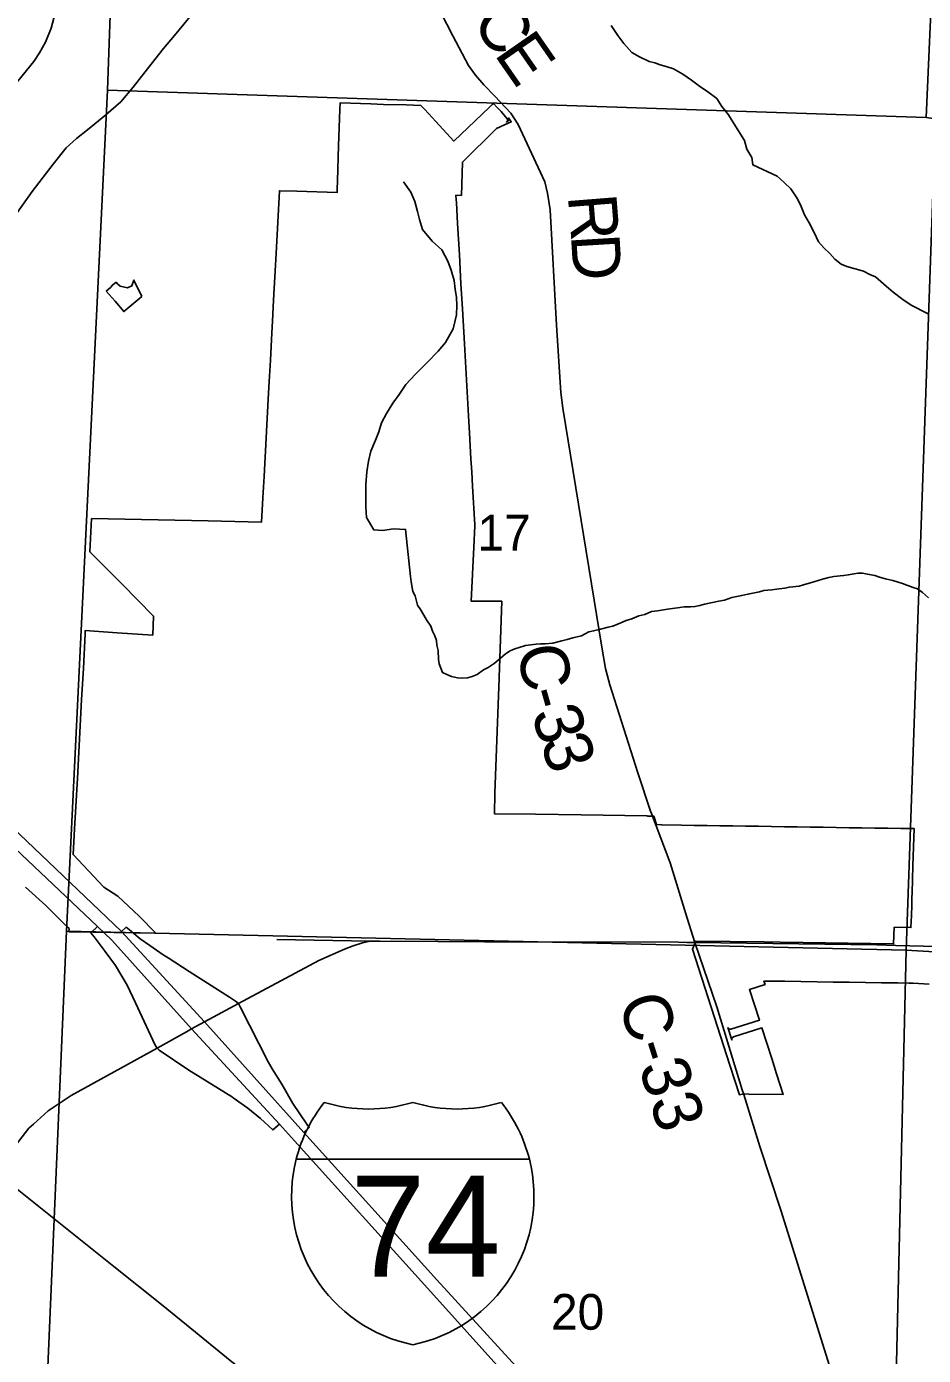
# Model space of a CAD drawing. Extents: x -7.5 to 26.5, y 3.5 to 25.5.
# Drawn here: x -4.268 to -3.216, y 21.705 to 23.263 of the extents above; entities that cross this region are included whole.
import ezdxf

# ---------------------------------------------------------------- set-up
doc = ezdxf.new("R2010")
doc.units = 0
for name, color, linetype in [('GM_X_City_Street', 7, 'Continuous'), ('GM_X_Corporation', 7, 'Continuous'), ('GM_X_County_Road', 7, 'Continuous'), ('GM_X_County_Road_Text', 7, 'Continuous'), ('GM_X_Interchange_Ramps', 7, 'Continuous'), ('GM_X_Interstate_Location', 7, 'Continuous'), ('GM_X_Interstate_Route', 7, 'Continuous'), ('GM_X_Interstate_Shield', 7, 'Continuous'), ('GM_X_Minor_River', 7, 'Continuous'), ('GM_X_Section_Text', 7, 'Continuous'), ('GM_X_US_Route', 7, 'Continuous')]:
    doc.layers.add(name, color=color, linetype=linetype)

msp = doc.modelspace()

# ---------------------------------------------------------------- linework, layer by layer
at = {"layer": 'GM_X_City_Street'}
msp.add_line((-3.9745, 22.1926), (-3.8649, 22.1905), dxfattribs=at)
at = {"layer": 'GM_X_Corporation'}
for points in [[(-4.138, 24.1781), (-3.1693, 24.148), (-3.2132, 23.1565), (-4.1729, 23.1886)], [(-4.1729, 23.1886), (-3.2132, 23.1565), (-3.2023, 23.155), (-3.2367, 22.18), (-4.2212, 22.2025)], [(-3.2023, 23.155), (-2.1999, 23.1078), (-2.2479, 22.1217), (-3.2367, 22.18)], [(-4.2212, 22.2025), (-3.2367, 22.18), (-3.2602, 21.1789), (-4.2641, 21.1987)], [(-3.2367, 22.18), (-2.2479, 22.1217), (-2.268, 21.1618), (-3.2602, 21.1789)]]:
    msp.add_lwpolyline(points, close=True, dxfattribs=at)
msp.add_lwpolyline([(-4.269, 22.2541), (-4.2451, 22.2323), (-4.2206, 22.2079), (-4.2181, 22.2054), (-4.2183, 22.2016), (-4.2144, 22.2015), (-4.1162, 22.2001), (-4.136, 22.22), (-4.1609, 22.2432), (-4.1774, 22.2538), (-4.2133, 22.2921), (-4.2125, 22.307), (-4.2117, 22.3223), (-4.2082, 22.3813), (-4.2033, 22.4739), (-4.2013, 22.5105), (-4.1992, 22.551), (-4.199, 22.555), (-4.1618, 22.5524), (-4.12, 22.5496), (-4.1189, 22.5716), (-4.1563, 22.6098), (-4.1937, 22.6473), (-4.1916, 22.6862), (-4.0548, 22.6836), (-3.9923, 22.6822), (-3.9908, 22.7107), (-3.9894, 22.7356), (-3.9886, 22.7507), (-3.9878, 22.7659), (-3.987, 22.781), (-3.9862, 22.7961), (-3.9853, 22.8112), (-3.9845, 22.8264), (-3.9834, 22.8472), (-3.9821, 22.8719), (-3.9803, 22.9042), (-3.9796, 22.9178), (-3.9783, 22.9426), (-3.9753, 22.997), (-3.9714, 23.0707), (-3.9512, 23.0701), (-3.9039, 23.0686), (-3.9038, 23.0714), (-3.9038, 23.0718), (-3.903, 23.0948), (-3.9024, 23.1107), (-3.902, 23.1235), (-3.9005, 23.1662), (-3.9003, 23.1738), (-3.8641, 23.1726), (-3.8494, 23.1721), (-3.8227, 23.1714), (-3.8055, 23.1709), (-3.801, 23.166), (-3.788, 23.1519), (-3.7671, 23.1291), (-3.7253, 23.1686), (-3.7219, 23.1719), (-3.7205, 23.1732), (-3.716, 23.1684), (-3.7116, 23.1637), (-3.708, 23.1596), (-3.7046, 23.1553), (-3.7044, 23.1549), (-3.7042, 23.1545), (-3.7041, 23.1541), (-3.704, 23.1537), (-3.7041, 23.1532), (-3.7042, 23.1528), (-3.7043, 23.1524), (-3.7046, 23.152), (-3.7047, 23.1519), (-3.705, 23.1515), (-3.7054, 23.1512), (-3.7044, 23.1518), (-3.7038, 23.1522), (-3.7034, 23.1525), (-3.7031, 23.1528), (-3.7028, 23.1531), (-3.7026, 23.1536), (-3.7025, 23.154), (-3.7024, 23.1544), (-3.7024, 23.1549), (-3.7025, 23.1553), (-3.7027, 23.1558), (-3.7029, 23.1562), (-3.6997, 23.1514), (-3.7031, 23.1499), (-3.717, 23.1437), (-3.7569, 23.1042), (-3.758, 23.0652), (-3.7645, 23.0654), (-3.7642, 23.06), (-3.764, 23.0569), (-3.7626, 23.0322), (-3.7605, 22.9954), (-3.7586, 22.9615), (-3.7569, 22.9324), (-3.7546, 22.8912), (-3.7497, 22.8069), (-3.7486, 22.7867), (-3.7477, 22.7714), (-3.7469, 22.7562), (-3.746, 22.741), (-3.745, 22.7242), (-3.7424, 22.679), (-3.7424, 22.6779), (-3.7436, 22.6527), (-3.7465, 22.5892), (-3.7108, 22.5893), (-3.7139, 22.5), (-3.7139, 22.4989), (-3.7188, 22.3641), (-3.7195, 22.3401), (-3.6711, 22.3394), (-3.6176, 22.3386), (-3.5406, 22.3375), (-3.5395, 22.3374), (-3.5326, 22.3373), (-3.5292, 22.3273), (-3.5237, 22.327), (-3.5231, 22.327), (-3.5, 22.3266), (-3.4851, 22.3264), (-3.4701, 22.3262), (-3.4552, 22.326), (-3.44, 22.3257), (-3.4249, 22.3255), (-3.4097, 22.3253), (-3.3946, 22.3251), (-3.3794, 22.3248), (-3.3643, 22.3246), (-3.3491, 22.3244), (-3.334, 22.3242), (-3.3188, 22.3239), (-3.3037, 22.3237), (-3.2885, 22.3235), (-3.2734, 22.3233), (-3.2582, 22.323), (-3.2431, 22.3228), (-3.2274, 22.3226), (-3.2284, 22.2904), (-3.2287, 22.279), (-3.2298, 22.2469), (-3.2299, 22.242), (-3.2302, 22.2326), (-3.2306, 22.2208), (-3.2311, 22.2066), (-3.2507, 22.207), (-3.2515, 22.1873), (-3.3839, 22.1894), (-3.4028, 22.1897), (-3.4834, 22.1907), (-3.4872, 22.1812), (-3.4434, 22.0453), (-3.4376, 22.0272), (-3.4322, 22.0104), (-3.4269, 22.0114), (-3.421, 22.0113), (-3.3809, 22.0107), (-3.3886, 22.0349), (-3.3943, 22.0529), (-3.4001, 22.071), (-3.4058, 22.0889), (-3.4392, 22.0783), (-3.4396, 22.0781), (-3.4401, 22.0778), (-3.4404, 22.0775), (-3.4407, 22.0771), (-3.441, 22.0767), (-3.4411, 22.0762), (-3.4412, 22.0757), (-3.4411, 22.0752), (-3.441, 22.0747), (-3.4456, 22.0892), (-3.4454, 22.0887), (-3.4452, 22.0883), (-3.4448, 22.0879), (-3.4444, 22.0876), (-3.444, 22.0874), (-3.4435, 22.0872), (-3.443, 22.0872), (-3.4425, 22.0872), (-3.4421, 22.0873), (-3.4087, 22.0979), (-3.4144, 22.1161), (-3.4202, 22.134), (-3.4021, 22.1398), (-3.4034, 22.1438), (-3.398, 22.1438), (-3.3791, 22.1435), (-3.3602, 22.1432), (-3.3412, 22.143), (-3.3223, 22.1427), (-3.3034, 22.1425), (-3.2844, 22.1422), (-3.2655, 22.1419), (-3.2465, 22.1417), (-3.2337, 22.1415), (-3.2286, 22.1412), (-3.2097, 22.14)], dxfattribs=at)
at = {"layer": 'GM_X_County_Road'}
for p, q in [((-3.4843, 22.1889), (-3.4933, 22.2175)), ((-4.0542, 22.0988), (-4.0196, 22.1174))]:
    msp.add_line(p, q, dxfattribs=at)
for points in [[(-4.3557, 23.0673), (-4.3318, 23.1095), (-4.3115, 23.1487), (-4.2883, 23.1867), (-4.2592, 23.2222), (-4.2527, 23.2325), (-4.2455, 23.245), (-4.239, 23.2613), (-4.2197, 23.3335), (-4.2114, 23.3542), (-4.165, 23.4496), (-4.1546, 23.4697), (-4.148, 23.482), (-4.1366, 23.4992), (-4.1272, 23.5096), (-4.1173, 23.5179), (-4.0908, 23.54), (-4.0744, 23.5582), (-4.0689, 23.5712), (-4.0648, 23.5832)], [(-4.442, 22.6063), (-4.4334, 22.6189), (-4.4176, 22.654), (-4.3877, 22.7241), (-4.3725, 22.7693), (-4.3633, 22.8101), (-4.3488, 22.8633), (-4.342, 22.8894), (-4.3327, 22.9169), (-4.3053, 22.9874), (-4.2936, 23.0185), (-4.2858, 23.0352), (-4.2614, 23.0699), (-4.2366, 23.1021), (-4.2215, 23.121), (-4.2094, 23.1319), (-4.1964, 23.1423), (-4.1751, 23.1597), (-4.1572, 23.1752), (-4.1429, 23.1922), (-4.122, 23.2193), (-4.1074, 23.2375), (-4.0945, 23.253), (-4.0327, 23.3282)], [(-3.5353, 22.3402), (-3.5363, 22.3429), (-3.5514, 22.3881), (-3.5842, 22.4913), (-3.5891, 22.5104), (-3.5935, 22.5356), (-3.6393, 22.8156), (-3.6415, 22.8342), (-3.6466, 22.9131), (-3.6539, 23.0482), (-3.657, 23.0679), (-3.6604, 23.0812), (-3.6916, 23.1485), (-3.7002, 23.1618), (-3.7191, 23.1816), (-3.7317, 23.1948), (-3.7414, 23.2063), (-3.7499, 23.2176), (-3.768, 23.2524), (-3.7825, 23.2807)], [(-3.4933, 22.2175), (-3.5135, 22.2824), (-3.5353, 22.3402)], [(-4.0196, 22.1174), (-3.9252, 22.1679), (-3.8952, 22.1813), (-3.885, 22.1853), (-3.8739, 22.1886), (-3.8649, 22.1905)], [(-3.8649, 22.1905), (-3.8539, 22.1905), (-3.7859, 22.1902), (-3.731, 22.19), (-3.7224, 22.19)], [(-3.7224, 22.19), (-3.5035, 22.1893), (-3.494, 22.1891)], [(-3.494, 22.1891), (-3.4892, 22.189), (-3.4843, 22.1889)], [(-3.4288, 22.0164), (-3.4586, 22.1135), (-3.4843, 22.1889)], [(-3.4843, 22.1889), (-3.2712, 22.1863), (-3.2487, 22.1857), (-3.2, 22.1843), (-3.1124, 22.1784), (-3.0958, 22.1773), (-3.0867, 22.1766)], [(-4.0805, 22.0844), (-4.0745, 22.0878), (-4.0594, 22.096), (-4.0542, 22.0988)], [(-4.3045, 21.9204), (-4.2653, 21.9711), (-4.2599, 21.9759), (-4.2427, 21.9915), (-4.2156, 22.0097), (-4.1146, 22.0653), (-4.0805, 22.0844)], [(-3.3225, 21.6802), (-3.3837, 21.875), (-3.4084, 21.9498), (-3.4271, 22.0107), (-3.4288, 22.0164)], [(-4.3045, 21.9204), (-4.2849, 21.9046), (-4.1655, 21.8092), (-4.1097, 21.7644)], [(-4.1097, 21.7644), (-4.1035, 21.7594), (-4.07, 21.7319), (-4.0292, 21.6988), (-3.9899, 21.668), (-3.9853, 21.6643)]]:
    msp.add_lwpolyline(points, dxfattribs=at)
at = {"layer": 'GM_X_Interchange_Ramps'}
for points in [[(-4.1846, 22.2079), (-4.1927, 22.2005), (-4.1887, 22.1957), (-4.1757, 22.1785), (-4.1638, 22.162), (-4.1499, 22.1389), (-4.14, 22.1181), (-4.1172, 22.0687), (-4.1146, 22.0653)], [(-4.1423, 22.1996), (-4.1474, 22.2038), (-4.1513, 22.2069), (-4.1567, 22.202)], [(-4.1019, 22.1709), (-4.1076, 22.1746), (-4.1235, 22.1855), (-4.1346, 22.1932), (-4.1423, 22.1996)], [(-4.0196, 22.1174), (-4.0231, 22.1204), (-4.0298, 22.1251), (-4.0772, 22.1549), (-4.1019, 22.1709)], [(-3.9798, 22.041), (-3.9848, 22.0492), (-4.0173, 22.1134), (-4.0196, 22.1174)], [(-4.1146, 22.0653), (-4.1123, 22.0626), (-4.0777, 22.0393), (-4.0427, 22.0178), (-4.0266, 22.0075)], [(-3.9428, 21.9662), (-3.9364, 21.9721), (-3.9392, 21.9759), (-3.9557, 22.0004), (-3.9687, 22.0227), (-3.9798, 22.041)], [(-4.0266, 22.0075), (-4.0257, 22.0069), (-4.0083, 21.9946), (-3.9936, 21.9826), (-3.9792, 21.9692), (-3.9713, 21.9758)]]:
    msp.add_lwpolyline(points, dxfattribs=at)
at = {"layer": 'GM_X_Interstate_Route'}
for points in [[(-5.162, 23.2174), (-5.0899, 23.1819), (-5.0197, 23.1473), (-4.9468, 23.11), (-4.9056, 23.0854), (-4.8753, 23.0652), (-4.8477, 23.0451), (-4.824, 23.0227), (-4.803, 22.9999), (-4.7793, 22.9735), (-4.7534, 22.9389), (-4.7236, 22.8924), (-4.6911, 22.8389), (-4.6498, 22.7714), (-4.6034, 22.6963), (-4.5705, 22.6419), (-4.5253, 22.57), (-4.4885, 22.5169), (-4.4564, 22.477), (-4.4218, 22.4379), (-4.3854, 22.3993), (-4.349, 22.3629), (-4.1846, 22.2079)], [(-4.3448, 22.3814), (-4.1567, 22.202)], [(-4.1846, 22.2079), (-4.1678, 22.1919), (-4.0745, 22.0878), (-3.9713, 21.9758)], [(-4.1567, 22.202), (-4.0594, 22.096), (-3.9428, 21.9662), (-3.7871, 21.7934), (-3.5932, 21.5815), (-3.4445, 21.4153), (-3.3498, 21.3091), (-3.2949, 21.249), (-3.2506, 21.2025), (-3.2037, 21.1569), (-3.1576, 21.1144), (-3.1133, 21.0758), (-2.9944, 20.9805), (-2.7725, 20.8074), (-2.7357, 20.7786), (-2.6558, 20.7178), (-2.5166, 20.6214)], [(-3.9713, 21.9758), (-3.9537, 21.9563), (-3.798, 21.7835), (-3.6059, 21.5704), (-3.4554, 21.4053), (-3.3607, 21.2992), (-3.3058, 21.2391), (-3.2615, 21.1926), (-3.2146, 21.147), (-3.1685, 21.1044), (-3.1242, 21.0658), (-3.0115, 20.9737), (-2.7821, 20.7947), (-2.748, 20.7669)]]:
    msp.add_lwpolyline(points, dxfattribs=at)
at = {"layer": 'GM_X_Interstate_Shield'}
for p, q in [((-3.9517, 21.9349), (-3.6785, 21.9349)), ((-3.6785, 21.9349), (-3.9517, 21.9349)), ((-3.6785, 21.9349), (-3.9517, 21.9349))]:
    msp.add_line(p, q, dxfattribs=at)
for centre, start, end in [((-3.7796, 21.8913), 141.669, 165.8066), ((-3.867, 22.1713), 253.0091, 286.9909), ((-3.7632, 22.1713), 253.0091, 286.9909), ((-3.8506, 21.8913), 14.1934, 38.331), ((-3.7796, 21.8913), 165.8066, 258.463), ((-3.8506, 21.8913), 281.537, 14.1934)]:
    msp.add_arc(centre, 0.1776, start, end, dxfattribs=at)
at = {"layer": 'GM_X_Minor_River'}
for points in [[(-3.2964, 22.9793), (-3.3062, 22.9819), (-3.3129, 22.9848), (-3.3203, 22.9904), (-3.3262, 22.997), (-3.3328, 23.0033), (-3.3394, 23.0108), (-3.3447, 23.0216), (-3.3504, 23.0332), (-3.3558, 23.0425), (-3.3607, 23.0541), (-3.365, 23.0626), (-3.3719, 23.0731), (-3.3796, 23.0806), (-3.3881, 23.0877), (-3.4165, 23.1012), (-3.4178, 23.1096), (-3.4235, 23.1197), (-3.4262, 23.1297), (-3.4367, 23.1464), (-3.4449, 23.1599), (-3.4526, 23.1697), (-3.4587, 23.179), (-3.4691, 23.1866), (-3.4791, 23.1934), (-3.4884, 23.2005), (-3.4984, 23.2073), (-3.5096, 23.2138), (-3.5182, 23.2164), (-3.525, 23.2185), (-3.5314, 23.2206), (-3.5378, 23.2223), (-3.5494, 23.2277), (-3.5583, 23.2329), (-3.5678, 23.2435), (-3.5747, 23.2528), (-3.5827, 23.2645)], [(-3.8179, 22.6185), (-3.8236, 22.6736), (-3.8376, 22.6744), (-3.8506, 22.6724), (-3.8608, 22.673), (-3.8692, 22.6877), (-3.87, 22.7002), (-3.8701, 22.7128), (-3.8701, 22.7264), (-3.869, 22.7409), (-3.8672, 22.7537), (-3.8643, 22.7654), (-3.859, 22.7782), (-3.855, 22.788), (-3.8517, 22.7986), (-3.8458, 22.8095), (-3.8386, 22.8215), (-3.8312, 22.8319), (-3.8233, 22.8435), (-3.812, 22.8558), (-3.7984, 22.8695), (-3.7855, 22.8825), (-3.7766, 22.8926), (-3.7678, 22.9087), (-3.764, 22.9253), (-3.7634, 22.936), (-3.7639, 22.9455), (-3.7656, 22.9554), (-3.7665, 22.9653), (-3.77, 22.9775), (-3.7739, 22.9883), (-3.7812, 23.0014), (-3.7923, 23.0115), (-3.8038, 23.0255), (-3.8073, 23.037), (-3.8097, 23.0465), (-3.8128, 23.058), (-3.8175, 23.0691), (-3.826, 23.0811)], [(-3.2101, 22.9259), (-3.2179, 22.93), (-3.2246, 22.9336), (-3.231, 22.9365), (-3.2407, 22.9433), (-3.2518, 22.952), (-3.2603, 22.9587), (-3.2728, 22.9698), (-3.2792, 22.9727), (-3.2866, 22.9763), (-3.2964, 22.9793)], [(-4.1327, 22.9468), (-4.142, 22.966), (-4.1445, 22.9592), (-4.1495, 22.9567), (-4.1582, 22.9588), (-4.1611, 22.9616), (-4.163, 22.9635), (-4.1672, 22.9602), (-4.1696, 22.9572), (-4.1746, 22.9528)], [(-4.1746, 22.9528), (-4.1639, 22.9411), (-4.1599, 22.936), (-4.154, 22.929), (-4.1327, 22.9468)], [(-3.2107, 22.5932), (-3.2174, 22.5995), (-3.2233, 22.6039), (-3.2286, 22.6055), (-3.2361, 22.608), (-3.241, 22.6101), (-3.2459, 22.6118), (-3.2523, 22.6135), (-3.261, 22.6156), (-3.2678, 22.6174), (-3.2735, 22.6195), (-3.2799, 22.6208), (-3.2879, 22.6222), (-3.2928, 22.6223), (-3.2982, 22.6214), (-3.3043, 22.6204), (-3.31, 22.6194), (-3.3215, 22.6183), (-3.3272, 22.6173), (-3.3349, 22.6153), (-3.3449, 22.6122), (-3.3572, 22.6084), (-3.3622, 22.607), (-3.3736, 22.6059), (-3.379, 22.6045), (-3.3855, 22.6039), (-3.3943, 22.6027), (-3.4034, 22.6018), (-3.4088, 22.6005), (-3.4222, 22.5975), (-3.4295, 22.5962), (-3.441, 22.5935), (-3.4498, 22.5904), (-3.4563, 22.5894), (-3.4732, 22.5858), (-3.4786, 22.5844), (-3.4843, 22.5831), (-3.4897, 22.5829), (-3.4969, 22.5827), (-3.5019, 22.5821), (-3.5164, 22.5799), (-3.5283, 22.578), (-3.5351, 22.5771), (-3.5432, 22.5739), (-3.5501, 22.5722), (-3.5582, 22.5687), (-3.5651, 22.5666), (-3.5713, 22.5638), (-3.5806, 22.5599), (-3.5859, 22.5589), (-3.5951, 22.5566), (-3.6032, 22.5545), (-3.6086, 22.5535), (-3.6174, 22.5489), (-3.6274, 22.5465), (-3.6343, 22.5445), (-3.6405, 22.5428), (-3.6508, 22.5401), (-3.66, 22.5392), (-3.6653, 22.5394), (-3.6703, 22.5391), (-3.6829, 22.5373), (-3.6902, 22.5352), (-3.6956, 22.5335), (-3.701, 22.531), (-3.7064, 22.5277), (-3.7127, 22.5222), (-3.7197, 22.5164), (-3.7267, 22.5117), (-3.7321, 22.5088), (-3.7395, 22.5033), (-3.7453, 22.5009), (-3.751, 22.4995), (-3.7575, 22.499), (-3.7625, 22.4995), (-3.7696, 22.5012), (-3.7753, 22.5033), (-3.7802, 22.5057), (-3.784, 22.5157), (-3.785, 22.5211), (-3.7855, 22.5317), (-3.7868, 22.5378), (-3.7874, 22.5432), (-3.7891, 22.5489), (-3.792, 22.5543), (-3.7941, 22.5601), (-3.7992, 22.5674), (-3.8021, 22.5728), (-3.8061, 22.5798), (-3.8094, 22.5848), (-3.8125, 22.5955), (-3.815, 22.6009), (-3.8169, 22.612), (-3.8179, 22.6185)]]:
    msp.add_lwpolyline(points, dxfattribs=at)
at = {"layer": 'GM_X_US_Route'}
for points in [[(-5.162, 23.2174), (-5.0899, 23.1819), (-5.0197, 23.1473), (-4.9468, 23.11), (-4.9056, 23.0854), (-4.8753, 23.0652), (-4.8477, 23.0451), (-4.824, 23.0227), (-4.803, 22.9999), (-4.7793, 22.9735), (-4.7534, 22.9389), (-4.7236, 22.8924), (-4.6911, 22.8389), (-4.6498, 22.7714), (-4.6034, 22.6963), (-4.5705, 22.6419), (-4.5253, 22.57), (-4.4885, 22.5169), (-4.4564, 22.477), (-4.4218, 22.4379), (-4.3854, 22.3993), (-4.349, 22.3629), (-4.1846, 22.2079)], [(-4.1846, 22.2079), (-4.1678, 22.1919), (-4.0745, 22.0878), (-3.9713, 21.9758)], [(-3.9713, 21.9758), (-3.9537, 21.9563), (-3.798, 21.7835), (-3.6059, 21.5704), (-3.4554, 21.4053), (-3.3607, 21.2992), (-3.3058, 21.2391), (-3.2615, 21.1926), (-3.2146, 21.147), (-3.1685, 21.1044), (-3.1242, 21.0658), (-3.0115, 20.9737), (-2.7821, 20.7947), (-2.748, 20.7669)]]:
    msp.add_lwpolyline(points, dxfattribs=at)

# ---------------------------------------------------------------- texts
at = {"layer": 'GM_X_County_Road_Text'}
for s, height, rotation, p in [('C', 0.0568, 305.0159, (-3.7473, 23.2692)), ('E', 0.0568, 304.7697, (-3.7205, 23.2311)), ('R', 0.0568, 274.5624, (-3.6334, 23.0649)), ('D', 0.0568, 273.4602, (-3.6297, 23.0187)), ('C', 0.0568, 279.7217, (-3.6928, 22.5347)), ('-', 0.0568, 285.7805, (-3.6835, 22.4823)), ('3', 0.0568, 287.6857, (-3.6766, 22.4579)), ('3', 0.0568, 287.8918, (-3.6659, 22.4243)), ('C-33', 0.05682, 287.4565, (-3.5747, 22.1202))]:
    msp.add_text(s, height=height, rotation=rotation, dxfattribs=at).set_placement(p)
at = {"layer": 'GM_X_Interstate_Location'}
for s in ['.', '-', ',']:
    msp.add_text(s, height=0.000189, dxfattribs=at).set_placement((-3.8151, 21.8593))
msp.add_text('74', height=0.000189, rotation=0, dxfattribs=at).set_placement((-3.8538, 21.8201))
at = {"layer": 'GM_X_Interstate_Shield'}
msp.add_text('74', height=0.11837, dxfattribs=at).set_placement((-3.8882, 21.7973))
at = {"layer": 'GM_X_Section_Text'}
for s, p in [('17', (-3.7392, 22.6488)), ('20', (-3.653, 21.7349))]:
    msp.add_text(s, height=0.04186, rotation=0, dxfattribs=at).set_placement(p)

doc.saveas('drawing.dxf')
